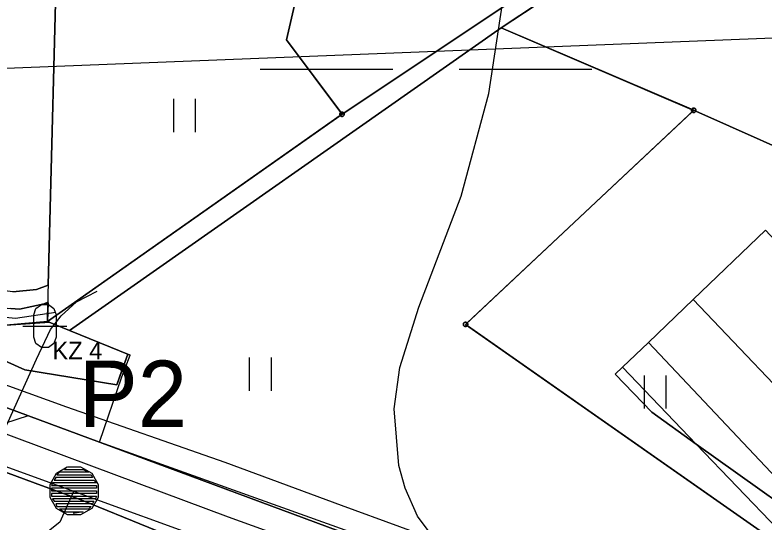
# Model space of a CAD drawing. Extents: x -645676 to -642474, y -1077513 to -1072613.
# Drawn here: x -644740.3 to -644570.9, y -1074844.5 to -1074729.8 of the extents above; entities that cross this region are included whole.
import ezdxf

# ---------------------------------------------------------------- set-up
doc = ezdxf.new("R2010")
doc.units = 0
for name, color, linetype in [('_elezni_n__tra_', 7, 'Continuous'), ('ELEKTRO', 7, 'Continuous'), ('KN', 7, 'Continuous'), ('KRAJ_ZELEN_STAV', 7, 'Continuous'), ('Krajinn__zele____popis___stav', 7, 'Continuous'), ('KULTURY_STAV', 7, 'Continuous'), ('KULTURY_ZNACKY', 7, 'Continuous'), ('Obvod_KP_', 7, 'Continuous'), ('OBVOD_PU', 7, 'Continuous'), ('PC_NAVRH', 7, 'Continuous'), ('PC_OBJ_POPIS_NAVRH', 7, 'Continuous'), ('PC_OBJ_PROP_NAVRH', 7, 'Continuous'), ('PC_STAN_NAVRH', 7, 'Continuous'), ('SDELOVACI', 7, 'Continuous'), ('Vodn__plocha___st_vaj_c_', 7, 'Continuous'), ('Vodn__tok', 7, 'Continuous'), ('VRSTEVNICE', 7, 'Continuous')]:
    doc.layers.add(name, color=color, linetype=linetype)

# ---------------------------------------------------------------- blocks, each defined once
blk = doc.blocks.new('$406')
blk.add_lwpolyline([(-0.19, 0.72), (0.2, 0.72), (0.54, 0.53), (0.73, 0.19), (0.73, -0.2), (0.54, -0.54), (0.2, -0.73), (-0.19, -0.73), (-0.53, -0.54), (-0.72, -0.2), (-0.72, 0.19), (-0.53, 0.53), (-0.2, 0.72), (-0.28, 0.64), (0.28, 0.64), (0.44, 0.56), (-0.44, 0.56), (-0.52, 0.48), (0.52, 0.48), (0.56, 0.4), (-0.55, 0.4), (-0.6, 0.32), (0.6, 0.32), (0.68, 0.24), (-0.59, 0.24), (-0.65, 0.24), (-0.68, 0.16), (0.59, 0.16), (0.68, 0.16), (0.68, 0.08), (-0.59, 0.08), (-0.68, 0.08), (-0.68, 0), (0.59, 0), (0.68, 0), (0.68, -0.08), (-0.59, -0.08), (-0.68, -0.08), (-0.68, -0.16), (0.59, -0.16), (0.68, -0.16), (0.65, -0.24), (-0.62, -0.24), (-0.65, -0.24), (-0.6, -0.32), (0.6, -0.32), (0.56, -0.4), (-0.55, -0.4), (-0.52, -0.48), (0.52, -0.48), (0.44, -0.56), (-0.44, -0.56), (-0.28, -0.64), (0.28, -0.64), (-0.02, -0.69)])
blk = doc.blocks.new('8$0300')
for p, q in [((-7.5, 0), (-1.5, 0)), ((1.5, 0), (7.5, 0))]:
    blk.add_line(p, q)
blk = doc.blocks.new('3$0600')
for p, q in [((-0.5, 1.5), (-0.5, 0)), ((0.5, 0), (0.5, 1.5))]:
    blk.add_line(p, q)
blk = doc.blocks.new('3$1600')
for points in [[(-0.5, 1.5), (-0.4, 1.79), (-0.15, 1.97), (0.16, 1.97), (0.41, 1.79), (0.51, 1.5), (0.51, 0.5), (0.41, 0.21), (0.16, 0.03), (-0.15, 0.03), (-0.4, 0.21), (-0.5, 0.5), (-0.5, 1.5)], [(-1, 1), (0.27, 1), (1, 1)]]:
    blk.add_lwpolyline(points)
blk = doc.blocks.new('$939')
for p, q in [((-2, -0.8), (-1.2, 0)), ((2, -0.8), (1.2, 0))]:
    blk.add_line(p, q)
blk.add_lwpolyline([(-2, 0.8), (-1.2, 0), (1.2, 0), (2, 0.8)])

msp = doc.modelspace()

# ---------------------------------------------------------------- linework, layer by layer
at = {"layer": '_elezni_n__tra_'}
msp.add_lwpolyline([(-645032.05, -1074719.88), (-645007.73, -1074729.17), (-644983.14, -1074736.55), (-644942.37, -1074750.02), (-644914.47, -1074760.84), (-644882.89, -1074772.03), (-644837.1, -1074789.71), (-644791.46, -1074806.27), (-644722.98, -1074831.82), (-644692.05, -1074843.35), (-644645.1, -1074860.33), (-644595.62, -1074879.05), (-644567.2, -1074889.68), (-644538.28, -1074900.75), (-644463.04, -1074928.93), (-644414.14, -1074947.15), (-644324.54, -1074980.78), (-644238.86, -1075012.25), (-644147.17, -1075045.91), (-644073.62, -1075073.69), (-644009.64, -1075097.37)], dxfattribs=at)
at = {"layer": 'ELEKTRO'}
msp.add_line((-644763.2, -1074742.66), (-644515.77, -1074732.93), dxfattribs=at)
at = {"layer": 'KN'}
for points in [[(-644561.86, -1074687.4), (-644630.29, -1074732.74), (-644727.89, -1074801.18), (-644732.93, -1074799.15), (-644666.71, -1074752.57), (-644666.68, -1074752.6), (-644666.62, -1074752.66), (-644666.55, -1074752.71), (-644666.47, -1074752.75), (-644666.39, -1074752.77), (-644666.3, -1074752.78), (-644666.21, -1074752.77), (-644666.13, -1074752.75), (-644666.05, -1074752.71), (-644665.98, -1074752.66), (-644665.92, -1074752.6), (-644665.87, -1074752.53), (-644665.83, -1074752.45), (-644665.81, -1074752.37), (-644665.8, -1074752.28), (-644665.81, -1074752.19), (-644665.83, -1074752.11), (-644665.87, -1074752.03), (-644665.89, -1074752), (-644627.91, -1074726.7)], [(-644556.49, -1074764.86), (-644586.31, -1074751.59), (-644586.3, -1074751.56), (-644586.28, -1074751.48), (-644586.27, -1074751.39), (-644586.28, -1074751.3), (-644586.3, -1074751.22), (-644586.34, -1074751.14), (-644586.39, -1074751.07), (-644586.45, -1074751.01), (-644586.52, -1074750.96), (-644586.6, -1074750.92), (-644586.68, -1074750.9), (-644586.77, -1074750.89), (-644586.86, -1074750.9), (-644586.94, -1074750.92), (-644587.02, -1074750.96), (-644587.09, -1074751.01), (-644587.15, -1074751.07), (-644587.2, -1074751.14), (-644587.23, -1074751.19), (-644630.29, -1074732.74), (-644561.86, -1074687.4)], [(-644627.91, -1074726.7), (-644665.89, -1074752), (-644665.92, -1074751.96), (-644665.98, -1074751.9), (-644666.05, -1074751.85), (-644666.13, -1074751.81), (-644666.21, -1074751.79), (-644666.3, -1074751.78), (-644666.39, -1074751.79), (-644666.47, -1074751.81), (-644666.55, -1074751.85), (-644666.6, -1074751.88), (-644678.86, -1074735.41), (-644675.47, -1074720.63)], [(-644583.74, -1074875.71), (-644721.17, -1074826.46), (-644716.09, -1074811.7), (-644714.21, -1074806.76), (-644727.89, -1074801.18), (-644630.29, -1074732.74), (-644587.23, -1074751.19), (-644587.24, -1074751.22), (-644587.26, -1074751.3), (-644587.27, -1074751.39), (-644587.26, -1074751.48), (-644587.24, -1074751.56), (-644587.2, -1074751.64), (-644587.15, -1074751.71), (-644587.13, -1074751.73), (-644638, -1074799.48), (-644638.04, -1074799.44), (-644638.11, -1074799.39), (-644638.19, -1074799.35), (-644638.27, -1074799.33), (-644638.36, -1074799.32), (-644638.45, -1074799.33), (-644638.53, -1074799.35), (-644638.61, -1074799.39), (-644638.68, -1074799.44), (-644638.74, -1074799.5), (-644638.79, -1074799.57), (-644638.83, -1074799.65), (-644638.85, -1074799.73), (-644638.86, -1074799.82), (-644638.85, -1074799.91), (-644638.83, -1074799.99), (-644638.79, -1074800.07), (-644638.74, -1074800.14), (-644638.68, -1074800.2), (-644638.61, -1074800.25), (-644638.53, -1074800.29), (-644638.45, -1074800.31), (-644638.36, -1074800.32), (-644638.27, -1074800.31), (-644638.19, -1074800.29), (-644638.11, -1074800.25), (-644638.04, -1074800.2), (-644637.98, -1074800.14), (-644637.95, -1074800.11), (-644558.41, -1074855.87)], [(-644570.53, -1074778.47), (-644586.87, -1074794.19), (-644597, -1074803.92), (-644602.85, -1074809.53), (-644604.49, -1074811.07), (-644596.26, -1074819.71), (-644586.21, -1074826.89), (-644558.41, -1074855.87), (-644637.95, -1074800.11), (-644637.93, -1074800.07), (-644637.89, -1074799.99), (-644637.87, -1074799.91), (-644637.86, -1074799.82), (-644637.87, -1074799.73), (-644637.89, -1074799.65), (-644637.93, -1074799.57), (-644637.98, -1074799.5), (-644638, -1074799.48), (-644587.13, -1074751.73), (-644587.09, -1074751.77), (-644587.02, -1074751.82), (-644586.94, -1074751.86), (-644586.86, -1074751.88), (-644586.77, -1074751.89), (-644586.68, -1074751.88), (-644586.6, -1074751.86), (-644586.52, -1074751.82), (-644586.45, -1074751.77), (-644586.39, -1074751.71), (-644586.34, -1074751.64), (-644586.31, -1074751.59), (-644556.49, -1074764.86)], [(-644586.76, -1074751.39), (-644586.77, -1074751.39), (-644586.78, -1074751.39), (-644586.78, -1074751.38), (-644586.77, -1074751.38), (-644586.76, -1074751.38), (-644586.76, -1074751.39)], [(-644666.31, -1074752.29), (-644666.3, -1074752.28), (-644666.29, -1074752.27), (-644666.29, -1074752.28), (-644666.29, -1074752.29), (-644666.3, -1074752.29), (-644666.31, -1074752.29)], [(-644666.29, -1074752.27), (-644666.3, -1074752.28), (-644666.31, -1074752.27), (-644666.3, -1074752.27), (-644666.29, -1074752.27)]]:
    msp.add_lwpolyline(points, dxfattribs=at)
for points in [[(-644666.6, -1074751.88), (-644666.62, -1074751.9), (-644666.68, -1074751.96), (-644666.73, -1074752.03), (-644666.77, -1074752.11), (-644666.79, -1074752.19), (-644666.8, -1074752.28), (-644666.79, -1074752.37), (-644666.77, -1074752.45), (-644666.73, -1074752.53), (-644666.71, -1074752.57), (-644732.93, -1074799.15), (-644730.59, -1074707.25), (-644730.58, -1074707.25), (-644730.49, -1074707.24), (-644730.41, -1074707.22), (-644730.33, -1074707.18), (-644730.26, -1074707.13), (-644730.2, -1074707.07), (-644730.15, -1074707), (-644730.11, -1074706.92), (-644730.1, -1074706.87), (-644675.47, -1074720.63), (-644678.86, -1074735.41)], [(-644666.31, -1074752.27), (-644666.31, -1074752.28), (-644666.31, -1074752.29), (-644666.71, -1074752.57), (-644666.73, -1074752.53), (-644666.77, -1074752.45), (-644666.79, -1074752.37), (-644666.8, -1074752.28), (-644666.79, -1074752.19), (-644666.77, -1074752.11), (-644666.73, -1074752.03), (-644666.68, -1074751.96), (-644666.62, -1074751.9), (-644666.6, -1074751.88)], [(-644666.71, -1074752.57), (-644666.31, -1074752.29), (-644666.3, -1074752.29), (-644666.29, -1074752.29), (-644666.29, -1074752.28), (-644666.29, -1074752.27), (-644665.89, -1074752), (-644665.87, -1074752.03), (-644665.83, -1074752.11), (-644665.81, -1074752.19), (-644665.8, -1074752.28), (-644665.81, -1074752.37), (-644665.83, -1074752.45), (-644665.87, -1074752.53), (-644665.92, -1074752.6), (-644665.98, -1074752.66), (-644666.05, -1074752.71), (-644666.13, -1074752.75), (-644666.21, -1074752.77), (-644666.3, -1074752.78), (-644666.39, -1074752.77), (-644666.47, -1074752.75), (-644666.55, -1074752.71), (-644666.62, -1074752.66), (-644666.68, -1074752.6)], [(-644665.89, -1074752), (-644666.29, -1074752.27), (-644666.3, -1074752.27), (-644666.31, -1074752.27), (-644666.6, -1074751.88), (-644666.55, -1074751.85), (-644666.47, -1074751.81), (-644666.39, -1074751.79), (-644666.3, -1074751.78), (-644666.21, -1074751.79), (-644666.13, -1074751.81), (-644666.05, -1074751.85), (-644665.98, -1074751.9), (-644665.92, -1074751.96)], [(-644586.78, -1074751.39), (-644586.78, -1074751.4), (-644587.13, -1074751.73), (-644587.15, -1074751.71), (-644587.2, -1074751.64), (-644587.24, -1074751.56), (-644587.26, -1074751.48), (-644587.27, -1074751.39), (-644587.26, -1074751.3), (-644587.24, -1074751.22), (-644587.23, -1074751.19)], [(-644586.31, -1074751.59), (-644586.76, -1074751.39), (-644586.76, -1074751.38), (-644586.77, -1074751.38), (-644586.78, -1074751.38), (-644586.78, -1074751.39), (-644587.23, -1074751.19), (-644587.2, -1074751.14), (-644587.15, -1074751.07), (-644587.09, -1074751.01), (-644587.02, -1074750.96), (-644586.94, -1074750.92), (-644586.86, -1074750.9), (-644586.77, -1074750.89), (-644586.68, -1074750.9), (-644586.6, -1074750.92), (-644586.52, -1074750.96), (-644586.45, -1074751.01), (-644586.39, -1074751.07), (-644586.34, -1074751.14), (-644586.3, -1074751.22), (-644586.28, -1074751.3), (-644586.27, -1074751.39), (-644586.28, -1074751.48), (-644586.3, -1074751.56)], [(-644586.31, -1074751.59), (-644586.34, -1074751.64), (-644586.39, -1074751.71), (-644586.45, -1074751.77), (-644586.52, -1074751.82), (-644586.6, -1074751.86), (-644586.68, -1074751.88), (-644586.77, -1074751.89), (-644586.86, -1074751.88), (-644586.94, -1074751.86), (-644587.02, -1074751.82), (-644587.09, -1074751.77), (-644587.13, -1074751.73), (-644586.78, -1074751.4), (-644586.77, -1074751.4), (-644586.76, -1074751.4), (-644586.76, -1074751.39)], [(-644586.76, -1074751.39), (-644586.76, -1074751.4), (-644586.77, -1074751.4), (-644586.78, -1074751.4), (-644586.77, -1074751.39)], [(-644586.77, -1074751.39), (-644586.78, -1074751.4), (-644586.78, -1074751.39)], [(-644666.3, -1074752.28), (-644666.31, -1074752.29), (-644666.31, -1074752.28), (-644666.31, -1074752.27)], [(-644541.72, -1074809.3), (-644551.89, -1074818.62), (-644554.75, -1074821.24), (-644558.17, -1074824.38), (-644586.87, -1074794.19), (-644570.53, -1074778.47)], [(-644558.17, -1074824.38), (-644557.26, -1074825.34), (-644559.51, -1074827.53), (-644562.13, -1074830.08), (-644556.68, -1074835.7), (-644547.34, -1074845.33), (-644552.95, -1074850.62), (-644597, -1074803.92), (-644586.87, -1074794.19)], [(-644638, -1074799.48), (-644638.35, -1074799.81), (-644638.36, -1074799.81), (-644638.37, -1074799.81), (-644638.37, -1074799.82), (-644638.37, -1074799.83), (-644638.36, -1074799.83), (-644638.35, -1074799.83), (-644637.95, -1074800.11), (-644637.98, -1074800.14), (-644638.04, -1074800.2), (-644638.11, -1074800.25), (-644638.19, -1074800.29), (-644638.27, -1074800.31), (-644638.36, -1074800.32), (-644638.45, -1074800.31), (-644638.53, -1074800.29), (-644638.61, -1074800.25), (-644638.68, -1074800.2), (-644638.74, -1074800.14), (-644638.79, -1074800.07), (-644638.83, -1074799.99), (-644638.85, -1074799.91), (-644638.86, -1074799.82), (-644638.85, -1074799.73), (-644638.83, -1074799.65), (-644638.79, -1074799.57), (-644638.74, -1074799.5), (-644638.68, -1074799.44), (-644638.61, -1074799.39), (-644638.53, -1074799.35), (-644638.45, -1074799.33), (-644638.36, -1074799.32), (-644638.27, -1074799.33), (-644638.19, -1074799.35), (-644638.11, -1074799.39), (-644638.04, -1074799.44)], [(-644637.95, -1074800.11), (-644638.35, -1074799.83), (-644638.35, -1074799.82), (-644638.35, -1074799.81), (-644638, -1074799.48), (-644637.98, -1074799.5), (-644637.93, -1074799.57), (-644637.89, -1074799.65), (-644637.87, -1074799.73), (-644637.86, -1074799.82), (-644637.87, -1074799.91), (-644637.89, -1074799.99), (-644637.93, -1074800.07)], [(-644638.35, -1074799.81), (-644638.36, -1074799.82), (-644638.35, -1074799.83), (-644638.36, -1074799.83), (-644638.37, -1074799.83), (-644638.37, -1074799.82), (-644638.37, -1074799.81), (-644638.36, -1074799.81)], [(-644638.35, -1074799.83), (-644638.36, -1074799.82), (-644638.35, -1074799.81), (-644638.35, -1074799.82)], [(-644552.95, -1074850.62), (-644586.21, -1074826.89), (-644602.85, -1074809.53), (-644597, -1074803.92)], [(-644586.21, -1074826.89), (-644596.26, -1074819.71), (-644604.49, -1074811.07), (-644602.85, -1074809.53)], [(-644552.95, -1074850.62), (-644558.41, -1074855.87), (-644586.21, -1074826.89)]]:
    msp.add_lwpolyline(points, close=True, dxfattribs=at)
at = {"layer": 'KRAJ_ZELEN_STAV'}
msp.add_lwpolyline([(-644748.99, -1074805.18), (-644750.56, -1074799.84), (-644742.26, -1074800.02), (-644732.46, -1074799.34), (-644714.76, -1074806.54), (-644717.25, -1074813.49), (-644738.03, -1074810.09), (-644748.99, -1074805.18)], dxfattribs=at)
at = {"layer": 'KULTURY_STAV'}
for points in [[(-644709.44, -1074581.14), (-644730.58, -1074706.75), (-644732.72, -1074790.92), (-644735.42, -1074791.91), (-644740.74, -1074792.45), (-644752.88, -1074790.98), (-644762.52, -1074788.42), (-644782.83, -1074781.15), (-644828.75, -1074765.49), (-644872.55, -1074750.05), (-644898.87, -1074740.63), (-644904.54, -1074739.03), (-644918.57, -1074735.07), (-644919.51, -1074734.95), (-644939.69, -1074732.49), (-644943.82, -1074722.71), (-644942.47, -1074718.46), (-644938.39, -1074705.57), (-644930.04, -1074685.77), (-644963.2, -1074674.74), (-644974.18, -1074672.5), (-644977.8, -1074671.77), (-645004.38, -1074666.35), (-645021.55, -1074710.42)], [(-644561.58, -1074683.89), (-644578.53, -1074694.83), (-644583.08, -1074694.09), (-644583.78, -1074698.22), (-644627.91, -1074726.7), (-644666.3, -1074752.28), (-644678.86, -1074735.41), (-644675.47, -1074720.63), (-644730.58, -1074706.75), (-644709.44, -1074581.14)], [(-644561.58, -1074683.89), (-644561.86, -1074687.4), (-644574.15, -1074695.54), (-644584.5, -1074702.4), (-644630.29, -1074732.74), (-644727.89, -1074801.18), (-644732.93, -1074799.15), (-644666.3, -1074752.28), (-644627.91, -1074726.7), (-644583.78, -1074698.22), (-644578.53, -1074694.83), (-644561.58, -1074683.89)], [(-644558.41, -1074855.87), (-644638.36, -1074799.82), (-644590.47, -1074754.87), (-644586.77, -1074751.39), (-644630.29, -1074732.74), (-644609.62, -1074719.05), (-644592.8, -1074707.9), (-644589.92, -1074705.99), (-644589.27, -1074705.56), (-644584.5, -1074702.4), (-644585.16, -1074706.24), (-644585.25, -1074706.77), (-644585.65, -1074709.13), (-644586.09, -1074711.73), (-644556.1, -1074716.78)], [(-645042.1, -1074704.59), (-645006.81, -1074719.35), (-644953.82, -1074740.03), (-644928.12, -1074749.58), (-644926.53, -1074750.17), (-644824.29, -1074788.25), (-644721.17, -1074826.46), (-644584.34, -1074877.29), (-644564.38, -1074883.03)], [(-644740.74, -1074792.45), (-644735.42, -1074791.91), (-644732.72, -1074790.92), (-644730.58, -1074706.75), (-644675.47, -1074720.63), (-644678.86, -1074735.41), (-644666.3, -1074752.28), (-644732.93, -1074799.15), (-644732.82, -1074794.77), (-644733.66, -1074795.17), (-644739.24, -1074796.41), (-644741.21, -1074796.25)], [(-644564.38, -1074883.03), (-644584.34, -1074877.29), (-644721.17, -1074826.46), (-644824.29, -1074788.25), (-644926.53, -1074750.17), (-644924.29, -1074751), (-644921.99, -1074747.84), (-644916.18, -1074742.45), (-644911.44, -1074741.81), (-644900.01, -1074745.4), (-644874.88, -1074755.82), (-644831.04, -1074771.79), (-644785.45, -1074788.31), (-644764.37, -1074795.64), (-644750.56, -1074799.84), (-644748.99, -1074805.18), (-644738.03, -1074810.09), (-644717.25, -1074813.49), (-644716.55, -1074811.53), (-644714.76, -1074806.54), (-644714.21, -1074806.76), (-644727.89, -1074801.18), (-644630.29, -1074732.74)], [(-644630.29, -1074732.74), (-644586.77, -1074751.39), (-644638.36, -1074799.82), (-644558.41, -1074855.87)], [(-644571.94, -1074905.75), (-644582.1, -1074898.35), (-644587.88, -1074894.73), (-644599.15, -1074887.69), (-644603.1, -1074886.21), (-644625.37, -1074877.88), (-644648.69, -1074869.15), (-644694.81, -1074851.99), (-644725.16, -1074839.61), (-644735.7, -1074835.71), (-644794.33, -1074814.01), (-644839.75, -1074796.97), (-644886, -1074780.15), (-644917.01, -1074767.86), (-644922.5, -1074768.65), (-644927.17, -1074769.32), (-644934.42, -1074774.52), (-644951.5, -1074803.22), (-644977.86, -1074847.29), (-645008.49, -1074897.01), (-645011.04, -1074900.91)], [(-644917.01, -1074767.86), (-644886, -1074780.15), (-644839.75, -1074796.97), (-644794.33, -1074814.01), (-644735.7, -1074835.71), (-644725.16, -1074839.61), (-644694.81, -1074851.99), (-644648.69, -1074869.15), (-644625.37, -1074877.88), (-644599.15, -1074887.69), (-644587.88, -1074894.73), (-644582.1, -1074898.35), (-644571.94, -1074905.75)], [(-644570.53, -1074778.47), (-644586.87, -1074794.19), (-644597, -1074803.92), (-644602.85, -1074809.53), (-644604.49, -1074811.07), (-644596.26, -1074819.71), (-644586.21, -1074826.89), (-644552.95, -1074850.62)], [(-644552.95, -1074850.62), (-644586.21, -1074826.89), (-644602.85, -1074809.53), (-644597, -1074803.92), (-644586.87, -1074794.19), (-644570.53, -1074778.47)], [(-644741.21, -1074796.25), (-644739.24, -1074796.41), (-644733.66, -1074795.17), (-644732.82, -1074794.77), (-644732.93, -1074799.15), (-644732.46, -1074799.34), (-644742.26, -1074800.02)], [(-644732.93, -1074799.15), (-644727.89, -1074801.18), (-644714.21, -1074806.76), (-644714.76, -1074806.54), (-644716.55, -1074811.53), (-644717.25, -1074813.49), (-644738.03, -1074810.09), (-644748.99, -1074805.18), (-644750.56, -1074799.84), (-644748.85, -1074799.88), (-644742.26, -1074800.02), (-644732.46, -1074799.34), (-644732.93, -1074799.15)], [(-644602.85, -1074809.53), (-644586.21, -1074826.89), (-644596.26, -1074819.71), (-644604.49, -1074811.07), (-644602.85, -1074809.53)]]:
    msp.add_lwpolyline(points, dxfattribs=at)
at = {"layer": 'Obvod_KP_'}
msp.add_lwpolyline([(-644564.49, -1074883.93), (-644583.74, -1074875.71), (-644721.17, -1074826.46), (-644716.09, -1074811.7), (-644714.21, -1074806.76), (-644727.89, -1074801.18), (-644732.93, -1074799.15), (-644730.58, -1074706.75), (-644709.44, -1074581.14)], dxfattribs=at)
at = {"layer": 'OBVOD_PU'}
msp.add_lwpolyline([(-644564.49, -1074883.93), (-644583.74, -1074875.71), (-644721.17, -1074826.46), (-644716.09, -1074811.7), (-644714.21, -1074806.76), (-644727.89, -1074801.18), (-644732.93, -1074799.15), (-644730.58, -1074706.75), (-644709.44, -1074581.14)], dxfattribs=at)
at = {"layer": 'PC_NAVRH'}
for points in [[(-644567.19, -1074898.23), (-644579.49, -1074893.18), (-644609.51, -1074881.01), (-644677.32, -1074855.63), (-644745, -1074831.03), (-644754.83, -1074829.35), (-644791.71, -1074816.01), (-644820.96, -1074805.79), (-644875.57, -1074788.7), (-644932.63, -1074770.57), (-645017.52, -1074743.9), (-645048.97, -1074734.32), (-645061.39, -1074728.88), (-645092.58, -1074713.99), (-645134.64, -1074690.69), (-645139.68, -1074688.36), (-645154.82, -1074684.34), (-645162.37, -1074683.15), (-645179.59, -1074665.73)], [(-644726.92, -1074837.45), (-644730.08, -1074844.59), (-644733.42, -1074847.24), (-644737.78, -1074848.88), (-644742.64, -1074849.14), (-644775.59, -1074839.85), (-644889.12, -1074805.55), (-644932.37, -1074792.86), (-644937.59, -1074792.15), (-644944.85, -1074793.38), (-644949.65, -1074796.55), (-644952.92, -1074800.84), (-644967.24, -1074824.68), (-645035.16, -1074931.94), (-645112.98, -1075054.64)]]:
    msp.add_lwpolyline(points, dxfattribs=at)
at = {"layer": 'SDELOVACI'}
msp.add_lwpolyline([(-645028.66, -1074706.96), (-645005.96, -1074713.92), (-644990.69, -1074716.08), (-644979.69, -1074719.8), (-644949.61, -1074734.04), (-644933, -1074740.83), (-644923.71, -1074743.9), (-644918.72, -1074745.46), (-644903.81, -1074752.12), (-644892.73, -1074756.82), (-644869.42, -1074765.85), (-644826.04, -1074782.12), (-644782.18, -1074798.29), (-644775.1, -1074800.98), (-644762.85, -1074806.13), (-644728.62, -1074818.48), (-644692.8, -1074831.01), (-644666.5, -1074840.69), (-644640.09, -1074850.4), (-644608.82, -1074862.69), (-644584.77, -1074871.19), (-644577.64, -1074873.63), (-644564.43, -1074876.66)], dxfattribs=at)
at = {"layer": 'Vodn__plocha___st_vaj_c_'}
msp.add_lwpolyline([(-644753.29, -1074795.27), (-644739.24, -1074796.41), (-644733.66, -1074795.17), (-644732.73, -1074794.93), (-644732.93, -1074799.15), (-644742.26, -1074800.02)], dxfattribs=at)
msp.add_lwpolyline([(-644753.29, -1074795.27), (-644739.24, -1074796.41), (-644733.66, -1074795.17), (-644732.73, -1074794.93), (-644732.93, -1074799.15), (-644742.26, -1074800.02)], dxfattribs=at)
at = {"layer": 'Vodn__tok'}
for points in [[(-645118.46, -1075054.04), (-645116, -1075050.01), (-645085.27, -1075000.55), (-645046.98, -1074940.37), (-645020.72, -1074899.28), (-645016.84, -1074893.24), (-644984.96, -1074842.87), (-644959.03, -1074802.05), (-644937.04, -1074767.99), (-644934.18, -1074763.89), (-644927.51, -1074752.73), (-644922.7, -1074746.9), (-644916.92, -1074741.6), (-644911.15, -1074740.87), (-644899.76, -1074744.07), (-644872.06, -1074754.98), (-644827.55, -1074771.19), (-644782.23, -1074787.3), (-644761.55, -1074794.86), (-644753.14, -1074797.12), (-644740.1, -1074798.4), (-644731, -1074797.09)], [(-644743.22, -1074825.06), (-644735.39, -1074807.69), (-644732.21, -1074800.94), (-644729.81, -1074797.87), (-644726.36, -1074794.74), (-644721.66, -1074792.32)]]:
    msp.add_lwpolyline(points, dxfattribs=at)
at = {"layer": 'VRSTEVNICE'}
msp.add_lwpolyline([(-644622.43, -1074911.53), (-644625.14, -1074903.84), (-644639.66, -1074873.08), (-644640.38, -1074865.39), (-644640.09, -1074855.42), (-644649.21, -1074843.17), (-644652.05, -1074836.9), (-644653.48, -1074831.77), (-644654.48, -1074818.96), (-644653.19, -1074809.56), (-644648.92, -1074795.89), (-644639.38, -1074770.82), (-644633.11, -1074747.6), (-644629.98, -1074727.24), (-644630.26, -1074716.55), (-644634.25, -1074699.89), (-644640.95, -1074688.5), (-644645.79, -1074681.66), (-644651.77, -1074674.83), (-644663.88, -1074663.15), (-644673.42, -1074651.18), (-644687.09, -1074630.25), (-644695.49, -1074616.15), (-644707.6, -1074591.08)], dxfattribs=at)

# ---------------------------------------------------------------- block references
at = {"layer": 'KULTURY_ZNACKY', "xscale": 5, "yscale": 5}
for name, p in [('8$0300', (-644647.34, -1074742.11)), ('3$0600', (-644701.94, -1074756.32)), ('3$1600', (-644733.51, -1074805.19)), ('3$0600', (-644684.77, -1074814.82)), ('3$0600', (-644595.5, -1074818.85))]:
    msp.add_blockref(name, p, dxfattribs=at)
at = {"layer": 'PC_OBJ_PROP_NAVRH', "xscale": 5, "yscale": 5.000000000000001, "rotation": 63.192623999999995}
msp.add_blockref('$939', (-644745.36, -1074827.6), dxfattribs=at)
at = {"layer": 'PC_STAN_NAVRH', "xscale": 7.5, "yscale": 7.5}
msp.add_blockref('$406', (-644726.92, -1074837.45), dxfattribs=at)

# ---------------------------------------------------------------- texts
at = {"layer": 'Krajinn__zele____popis___stav'}
msp.add_text('KZ 4', height=4, dxfattribs=at).set_placement((-644731.79, -1074807.75))
at = {"layer": 'PC_OBJ_POPIS_NAVRH'}
msp.add_text('P2', height=15, dxfattribs=at).set_placement((-644725.86, -1074823.02))

doc.saveas('drawing.dxf')
